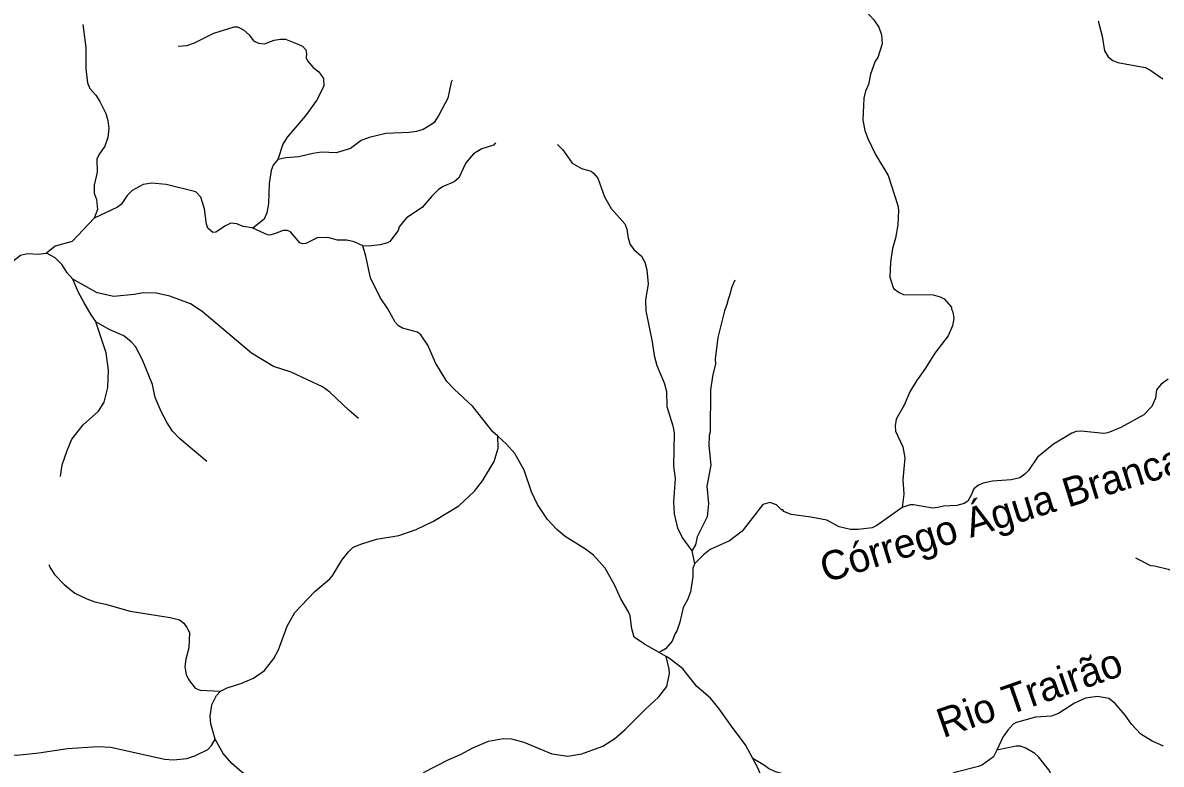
# Model space of a CAD drawing. Extents: x 500 to 555.2, y 9115.7 to 9171.
# Drawn here: x 535.68 to 543.48, y 9161.84 to 9166.92 of the extents above; entities that cross this region are included whole.
import ezdxf
from ezdxf.enums import TextEntityAlignment as Align

# ---------------------------------------------------------------- set-up
doc = ezdxf.new("R2010")
doc.units = 0
doc.header["$LTSCALE"] = 0.064
doc.layers.add('61', color=7, linetype='Continuous')
doc.layers.add('7', color=7, linetype='Continuous', lineweight=25)

msp = doc.modelspace()

# ---------------------------------------------------------------- linework, layer by layer
at = {"layer": '7'}
for points in [[(541.3584, 9167.1824), (541.4152, 9167.0604), (541.4647, 9166.992), (541.5154, 9166.9378), (541.5488, 9166.8872), (541.5662, 9166.8361), (541.5711, 9166.7728), (541.5415, 9166.6808), (541.5235, 9166.6549), (541.4916, 9166.566), (541.4778, 9166.4955), (541.4579, 9166.4484), (541.4463, 9166.4008), (541.4384, 9166.2509), (541.4524, 9166.1792), (541.4728, 9166.1243), (541.5263, 9166.0156), (541.6124, 9165.871)], [(543.0525, 9166.9304), (543.0672, 9166.8699), (543.0803, 9166.8257), (543.0965, 9166.7257), (543.1199, 9166.685), (543.153, 9166.66), (543.1876, 9166.6458), (543.3737, 9166.6108), (543.4063, 9166.5957), (543.4949, 9166.533)], [(536.0928, 9166.9051), (536.1139, 9166.7475), (536.114, 9166.6027), (536.1252, 9166.5054), (536.1398, 9166.4675), (536.1816, 9166.4207), (536.2086, 9166.3793), (536.2503, 9166.2954), (536.2649, 9166.2482), (536.2714, 9166.1932), (536.2648, 9166.1309), (536.2441, 9166.0731), (536.2026, 9166.0127), (536.1896, 9165.9832), (536.1909, 9165.894), (536.1701, 9165.8042), (536.1713, 9165.7493), (536.1864, 9165.7062), (536.1943, 9165.6381), (536.1695, 9165.5779)], [(536.7456, 9166.7573), (536.8047, 9166.7612), (536.8576, 9166.7806), (536.9916, 9166.8476), (537.1294, 9166.8901), (537.1532, 9166.8899), (537.1949, 9166.8689), (537.2326, 9166.8345), (537.2633, 9166.794), (537.2978, 9166.7777), (537.3376, 9166.7739), (537.4054, 9166.7986), (537.4489, 9166.8064), (537.4818, 9166.8047), (537.5629, 9166.7734), (537.5977, 9166.7568), (537.6207, 9166.7331), (537.6259, 9166.7081), (537.6233, 9166.6774), (537.6331, 9166.6559), (537.6712, 9166.6107), (537.7109, 9166.5809), (537.7427, 9166.5367), (537.7459, 9166.484), (537.6947, 9166.3854), (537.616, 9166.278), (537.4926, 9166.1335), (537.4642, 9166.0855), (537.4284, 9165.9815)], [(538.6243, 9166.5251), (538.6173, 9166.5117), (538.5944, 9166.401), (538.5335, 9166.2856), (538.5001, 9166.2338), (538.472, 9166.2138), (538.4265, 9166.1868), (538.3796, 9166.1723), (538.3303, 9166.1665), (538.1692, 9166.1586), (538.055, 9166.1325), (538.001, 9166.1105), (537.9275, 9166.0558), (537.8292, 9166.0264), (537.7296, 9166.0307), (537.6695, 9166.0222), (537.5733, 9165.998), (537.4837, 9165.993), (537.4284, 9165.9815)], [(538.9218, 9166.0946), (538.9079, 9166.0799), (538.8274, 9166.0547), (538.7718, 9166.0197), (538.7188, 9165.9569), (538.6702, 9165.8559), (538.6384, 9165.828), (538.563, 9165.7961), (538.5312, 9165.7756), (538.4842, 9165.7305), (538.4186, 9165.652), (538.3124, 9165.5816), (538.2613, 9165.5202), (538.2537, 9165.495), (538.1971, 9165.4191), (538.1805, 9165.4093), (538.132, 9165.3961), (538.051, 9165.3862), (538.0119, 9165.3891)], [(539.3463, 9166.0836), (539.3827, 9166.0475), (539.4471, 9165.9551), (539.5099, 9165.9198), (539.5761, 9165.8998), (539.593, 9165.888), (539.6221, 9165.8535), (539.6697, 9165.7252), (539.7137, 9165.6447), (539.8084, 9165.5407), (539.8225, 9165.5031), (539.8309, 9165.4419), (539.8456, 9165.3993), (539.8707, 9165.3644), (539.9227, 9165.3172), (539.946, 9165.2776), (539.9589, 9165.2245), (539.9668, 9165.1289), (539.9507, 9165.016), (539.951, 9164.9432), (539.9964, 9164.7306), (540.0082, 9164.6375), (540.028, 9164.5687), (540.0785, 9164.4511), (540.0935, 9164.39), (540.0952, 9164.2891), (540.1369, 9164.1549), (540.1458, 9164.1067), (540.1426, 9163.879), (540.1524, 9163.7935), (540.1426, 9163.6357), (540.1472, 9163.5527), (540.1691, 9163.4548), (540.2045, 9163.3823), (540.2682, 9163.2998)], [(537.4284, 9165.9815), (537.4277, 9165.9794), (537.3968, 9165.943), (537.3848, 9165.9062), (537.3691, 9165.8154), (537.3653, 9165.6798), (537.354, 9165.6157), (537.3353, 9165.571), (537.2587, 9165.5099)], [(537.2587, 9165.5099), (537.2545, 9165.5118), (537.1918, 9165.5218), (537.149, 9165.5401), (537.108, 9165.5433), (537.0697, 9165.5267), (537.0036, 9165.4824), (536.983, 9165.4816), (536.9501, 9165.5106), (536.9404, 9165.5384), (536.9275, 9165.642), (536.902, 9165.7219), (536.8683, 9165.7582), (536.6634, 9165.8092), (536.567, 9165.8192), (536.5067, 9165.8093), (536.4317, 9165.7678), (536.397, 9165.7332), (536.355, 9165.6717), (536.3304, 9165.6536), (536.1695, 9165.5779)], [(541.6124, 9165.871), (541.6793, 9165.6655), (541.6828, 9165.6328), (541.6793, 9165.5323), (541.6638, 9165.4422), (541.6436, 9165.3711), (541.6286, 9165.2772), (541.6237, 9165.1736), (541.6505, 9165.0971), (541.6881, 9165.0687), (541.7174, 9165.0554), (541.9222, 9165.0531), (541.9701, 9165.0405), (541.9977, 9165.025), (542.0466, 9164.9677), (542.047, 9164.9554), (542.0567, 9164.9376), (542.0632, 9164.8902), (542.0549, 9164.841), (542.0231, 9164.7714), (541.9321, 9164.6545), (541.8684, 9164.5501), (541.8076, 9164.4636), (541.7625, 9164.3876), (541.7223, 9164.2975), (541.6674, 9164.2001), (541.6615, 9164.1566), (541.6632, 9164.1193), (541.7136, 9164.0121), (541.727, 9163.9368), (541.714, 9163.7859), (541.7213, 9163.6869), (541.7095, 9163.5954)], [(536.1695, 9165.5779), (536.0196, 9165.4196), (535.903, 9165.3863), (535.8437, 9165.3382)], [(538.0119, 9165.3891), (537.9521, 9165.4174), (537.9029, 9165.4271), (537.8379, 9165.4289), (537.773, 9165.4466), (537.6989, 9165.4446), (537.6214, 9165.4044), (537.5977, 9165.4032), (537.5795, 9165.41), (537.5168, 9165.484), (537.4956, 9165.494), (537.4666, 9165.4941), (537.4066, 9165.471), (537.3747, 9165.4622), (537.358, 9165.4649), (537.2587, 9165.5099)], [(538.9367, 9164.085), (538.9043, 9164.1146), (538.7663, 9164.2871), (538.6372, 9164.4064), (538.5882, 9164.4589), (538.5091, 9164.5884), (538.4575, 9164.7076), (538.4106, 9164.7788), (538.3868, 9164.7971), (538.2841, 9164.8252), (538.2574, 9164.8405), (538.2337, 9164.8656), (538.1837, 9164.9569), (538.1319, 9165.0346), (538.0643, 9165.1697), (538.0331, 9165.3173), (538.0119, 9165.3891)], [(535.8437, 9165.3382), (535.8416, 9165.3365), (535.7897, 9165.3295), (535.7147, 9165.3335), (535.6651, 9165.3238), (535.5808, 9165.2566), (535.5267, 9165.2304), (535.5079, 9165.2305), (535.4004, 9165.2569)], [(536.0244, 9165.1612), (535.9859, 9165.2033), (535.9509, 9165.2584), (535.9026, 9165.3063), (535.8437, 9165.3382)], [(537.9832, 9164.2068), (537.9179, 9164.2613), (537.7865, 9164.386), (537.7362, 9164.4232), (537.5203, 9164.523), (537.4004, 9164.5617), (537.248, 9164.6542), (536.9116, 9164.9395), (536.8301, 9164.9927), (536.6891, 9165.0451), (536.5972, 9165.0647), (536.5067, 9165.0663), (536.4449, 9165.0549), (536.3064, 9165.0417), (536.1921, 9165.0673), (536.0244, 9165.1612)], [(536.1828, 9164.8673), (536.1821, 9164.8695), (536.1495, 9164.9162), (536.099, 9165.0026), (536.0643, 9165.0689), (536.0244, 9165.1612)], [(540.5623, 9165.1536), (540.5411, 9165.1072), (540.5263, 9165.0482), (540.5152, 9165.0212), (540.508, 9164.9877), (540.4904, 9164.9438), (540.4444, 9164.7611), (540.428, 9164.6125), (540.4295, 9164.5784), (540.4101, 9164.5069), (540.3954, 9164.4012), (540.3934, 9164.1139), (540.3869, 9164.0897), (540.3837, 9164.0208), (540.3983, 9163.8856), (540.3706, 9163.7414), (540.3804, 9163.6224), (540.3721, 9163.5314), (540.3036, 9163.3954), (540.2915, 9163.339), (540.2682, 9163.2998)], [(535.9408, 9163.8086), (535.9517, 9163.8875), (535.9848, 9163.9865), (536.0186, 9164.0635), (536.0947, 9164.1613), (536.2012, 9164.2564), (536.2401, 9164.3167), (536.2649, 9164.4189), (536.2697, 9164.537), (536.2531, 9164.6551), (536.1828, 9164.8673)], [(536.943, 9163.9117), (536.7565, 9164.0678), (536.7078, 9164.1201), (536.6699, 9164.1751), (536.6293, 9164.2538), (536.589, 9164.3498), (536.5694, 9164.4381), (536.5002, 9164.6133), (536.4544, 9164.6981), (536.4252, 9164.732), (536.3747, 9164.7726), (536.2745, 9164.8153), (536.1828, 9164.8673)], [(543.5316, 9164.475), (543.4833, 9164.442), (543.4515, 9164.4012), (543.4443, 9164.3461), (543.4213, 9164.2872), (543.3649, 9164.2302), (543.2069, 9164.1437), (543.1196, 9164.1067), (543.0901, 9164.1035), (542.9353, 9164.1197), (542.902, 9164.1162), (542.8718, 9164.1055), (542.7451, 9164.0292), (542.6363, 9163.9407), (542.574, 9163.8497), (542.5503, 9163.8246), (542.5154, 9163.7998), (542.4563, 9163.7851), (542.3284, 9163.7769), (542.2649, 9163.7626), (542.2321, 9163.7481), (542.1995, 9163.724), (542.1826, 9163.6813), (542.1585, 9163.6394), (542.1348, 9163.6222), (542.0829, 9163.6097), (541.993, 9163.6061), (541.9534, 9163.5958), (541.9175, 9163.5907), (541.7868, 9163.6138), (541.7631, 9163.6145), (541.7095, 9163.5954)], [(537.0367, 9162.338), (537.0817, 9162.3598), (537.1758, 9162.3896), (537.2625, 9162.4264), (537.3386, 9162.4789), (537.4023, 9162.5602), (537.4336, 9162.6193), (537.4937, 9162.782), (537.546, 9162.8764), (537.6842, 9163.0213), (537.7864, 9163.1073), (537.8071, 9163.1329), (537.8684, 9163.2353), (537.9133, 9163.2911), (537.9466, 9163.3231), (538.0058, 9163.3479), (538.1055, 9163.3779), (538.2597, 9163.4043), (538.3767, 9163.4446), (538.496, 9163.5023), (538.6711, 9163.6065), (538.7778, 9163.7082), (538.8314, 9163.7781), (538.9131, 9163.9118), (538.9398, 9164.0036), (538.9367, 9164.085)], [(539.2085, 9163.616), (539.1684, 9163.7026), (539.1189, 9163.8508), (539.0533, 9163.9656), (538.9975, 9164.0295), (538.9367, 9164.085)], [(540.0433, 9162.6012), (539.9417, 9162.6587), (539.8722, 9162.7075), (539.8563, 9162.764), (539.8438, 9162.8535), (539.833, 9162.8816), (539.7807, 9162.9703), (539.7383, 9163.0616), (539.6724, 9163.1796), (539.5929, 9163.2701), (539.5377, 9163.3108), (539.3983, 9163.3974), (539.3425, 9163.4451), (539.2785, 9163.514), (539.2085, 9163.616)], [(541.7095, 9163.5954), (541.5356, 9163.4724), (541.5037, 9163.4559), (541.4078, 9163.4457), (541.3547, 9163.4457), (541.2766, 9163.4635), (541.1924, 9163.5082), (541.0838, 9163.5307), (540.9473, 9163.5468), (540.8989, 9163.5674), (540.8907, 9163.5794), (540.882, 9163.5808), (540.8464, 9163.6139), (540.8026, 9163.629), (540.7544, 9163.6159), (540.6111, 9163.434), (540.5253, 9163.3673), (540.3929, 9163.3074), (540.348, 9163.2723), (540.2856, 9163.2106)], [(540.2682, 9163.2998), (540.2755, 9163.2563), (540.2856, 9163.2106)], [(543.3092, 9163.252), (543.4118, 9163.1982), (543.4384, 9163.1962), (543.5315, 9163.1723), (543.6155, 9163.1387), (543.6813, 9163.1049), (543.7732, 9163.0688), (543.8036, 9163.0632), (543.9786, 9162.9506), (544.0382, 9162.9223), (544.1563, 9162.8502), (544.1846, 9162.8266), (544.2225, 9162.7773)], [(535.8602, 9163.2063), (535.8699, 9163.1814), (535.8991, 9163.1357), (535.9651, 9163.0679), (536.038, 9163.0097), (536.12, 9162.9695), (536.1749, 9162.9493), (536.2483, 9162.9343), (536.4169, 9162.8849), (536.6911, 9162.8418), (536.7562, 9162.8264), (536.785, 9162.8036), (536.8068, 9162.7726), (536.824, 9162.7381), (536.8193, 9162.6337), (536.7982, 9162.5556), (536.7932, 9162.5039), (536.8019, 9162.4506), (536.8164, 9162.4167), (536.8632, 9162.3587), (536.8972, 9162.3439), (537.0367, 9162.338)], [(540.2856, 9163.2106), (540.275, 9163.1788), (540.2752, 9163.1211), (540.2577, 9163.0189), (540.237, 9162.9637)], [(540.237, 9162.9637), (540.2078, 9162.9111), (540.1855, 9162.809), (540.1672, 9162.7558), (540.1507, 9162.7288), (540.132, 9162.6787), (540.0859, 9162.6266), (540.0433, 9162.6012)], [(538.4279, 9161.7805), (538.6006, 9161.8693), (538.681, 9161.9038), (538.7664, 9161.9497), (538.8746, 9161.9939), (538.9736, 9162.012), (539.032, 9162.0102), (539.1152, 9161.987), (539.307, 9161.9073), (539.418, 9161.8925), (539.5129, 9161.9066), (539.6573, 9161.9605), (539.7385, 9162.0133), (539.8095, 9162.0744), (539.9496, 9162.2144), (540.0408, 9162.2973), (540.0955, 9162.3689), (540.113, 9162.4572), (540.1112, 9162.4868), (540.0918, 9162.5737)], [(540.6848, 9161.8761), (540.6349, 9161.9704), (540.5426, 9162.0914), (540.4557, 9162.2171), (540.3956, 9162.2903), (540.3023, 9162.3692), (540.2064, 9162.4893), (540.1132, 9162.5616), (540.0918, 9162.5737), (540.0433, 9162.6012)], [(536.9997, 9162.0076), (536.9702, 9162.1128), (536.9653, 9162.166), (536.9768, 9162.2433), (537.008, 9162.3065), (537.0367, 9162.338)], [(543.4971, 9161.961), (543.4951, 9161.9624), (543.4219, 9161.9937), (543.3442, 9162.0427), (543.2797, 9162.111), (543.2368, 9162.1723), (543.1682, 9162.2536), (543.1255, 9162.2877), (543.0481, 9162.3007), (542.9655, 9162.2892), (542.89, 9162.2548), (542.78, 9162.1843), (542.7331, 9162.1659), (542.6228, 9162.1593), (542.4925, 9162.1232), (542.4708, 9162.1108), (542.4332, 9162.071), (542.3999, 9162.0224), (542.357, 9161.9325)], [(535.4715, 9161.91), (535.5097, 9161.9025), (535.6399, 9161.8989), (535.7914, 9161.9149), (535.9877, 9161.9447), (536.1958, 9161.9578), (536.2855, 9161.9541), (536.6531, 9161.8721), (536.7144, 9161.8661), (536.8059, 9161.8747), (536.861, 9161.8945), (536.9498, 9161.9384), (536.975, 9161.9645), (536.9997, 9162.0076)], [(537.0694, 9161.3359), (537.1514, 9161.4018), (537.2796, 9161.4867), (537.3299, 9161.5121), (537.3789, 9161.5484), (537.3966, 9161.5747), (537.3964, 9161.6271), (537.3556, 9161.6674), (537.1827, 9161.7822), (537.115, 9161.8409), (537.0546, 9161.91), (536.9997, 9162.0076)], [(542.357, 9161.9325), (542.3358, 9161.8881), (542.2601, 9161.8333), (542.2324, 9161.8211), (542.0693, 9161.7804), (542.0431, 9161.7689), (541.9484, 9161.707), (541.8973, 9161.6877), (541.8409, 9161.6743), (541.7746, 9161.6692), (541.6624, 9161.6724), (541.3947, 9161.6381), (541.3672, 9161.6398), (541.2852, 9161.6628), (541.2282, 9161.6723), (541.1381, 9161.6627), (541.0913, 9161.6643), (541.047, 9161.6817), (541.0103, 9161.7182), (540.9189, 9161.764), (540.8403, 9161.7839), (540.7917, 9161.8063), (540.7658, 9161.8283), (540.6848, 9161.8761)], [(542.7702, 9160.0104), (542.7667, 9160.1419), (542.8061, 9160.2443), (542.8168, 9160.3391), (542.8594, 9160.4332), (542.8966, 9160.498), (542.9542, 9160.5675), (542.9818, 9160.6332), (542.9901, 9160.7077), (542.9801, 9160.813), (542.9325, 9160.9613), (542.9132, 9161.0509), (542.8996, 9161.1516), (542.8589, 9161.2756), (542.8092, 9161.5723), (542.7489, 9161.7348), (542.7145, 9161.7971), (542.6428, 9161.8868), (542.6176, 9161.9103), (542.557, 9161.9464), (542.5193, 9161.9594), (542.4897, 9161.9611), (542.357, 9161.9325)], [(540.8024, 9161.3973), (540.7952, 9161.5165), (540.7805, 9161.6397), (540.7239, 9161.8021), (540.6848, 9161.8761)]]:
    msp.add_lwpolyline(points, dxfattribs=at)

# ---------------------------------------------------------------- texts
at = {"layer": '61'}
for s, rotation, p in [('Córrego Água Branca', 17.241, (542.4192, 9163.4623)), ('Rio Trairão', 19.29, (542.6139, 9162.233))]:
    msp.add_text(s, height=0.2, rotation=rotation, dxfattribs=at).set_placement(p, align=Align.CENTER)

doc.saveas('drawing.dxf')
